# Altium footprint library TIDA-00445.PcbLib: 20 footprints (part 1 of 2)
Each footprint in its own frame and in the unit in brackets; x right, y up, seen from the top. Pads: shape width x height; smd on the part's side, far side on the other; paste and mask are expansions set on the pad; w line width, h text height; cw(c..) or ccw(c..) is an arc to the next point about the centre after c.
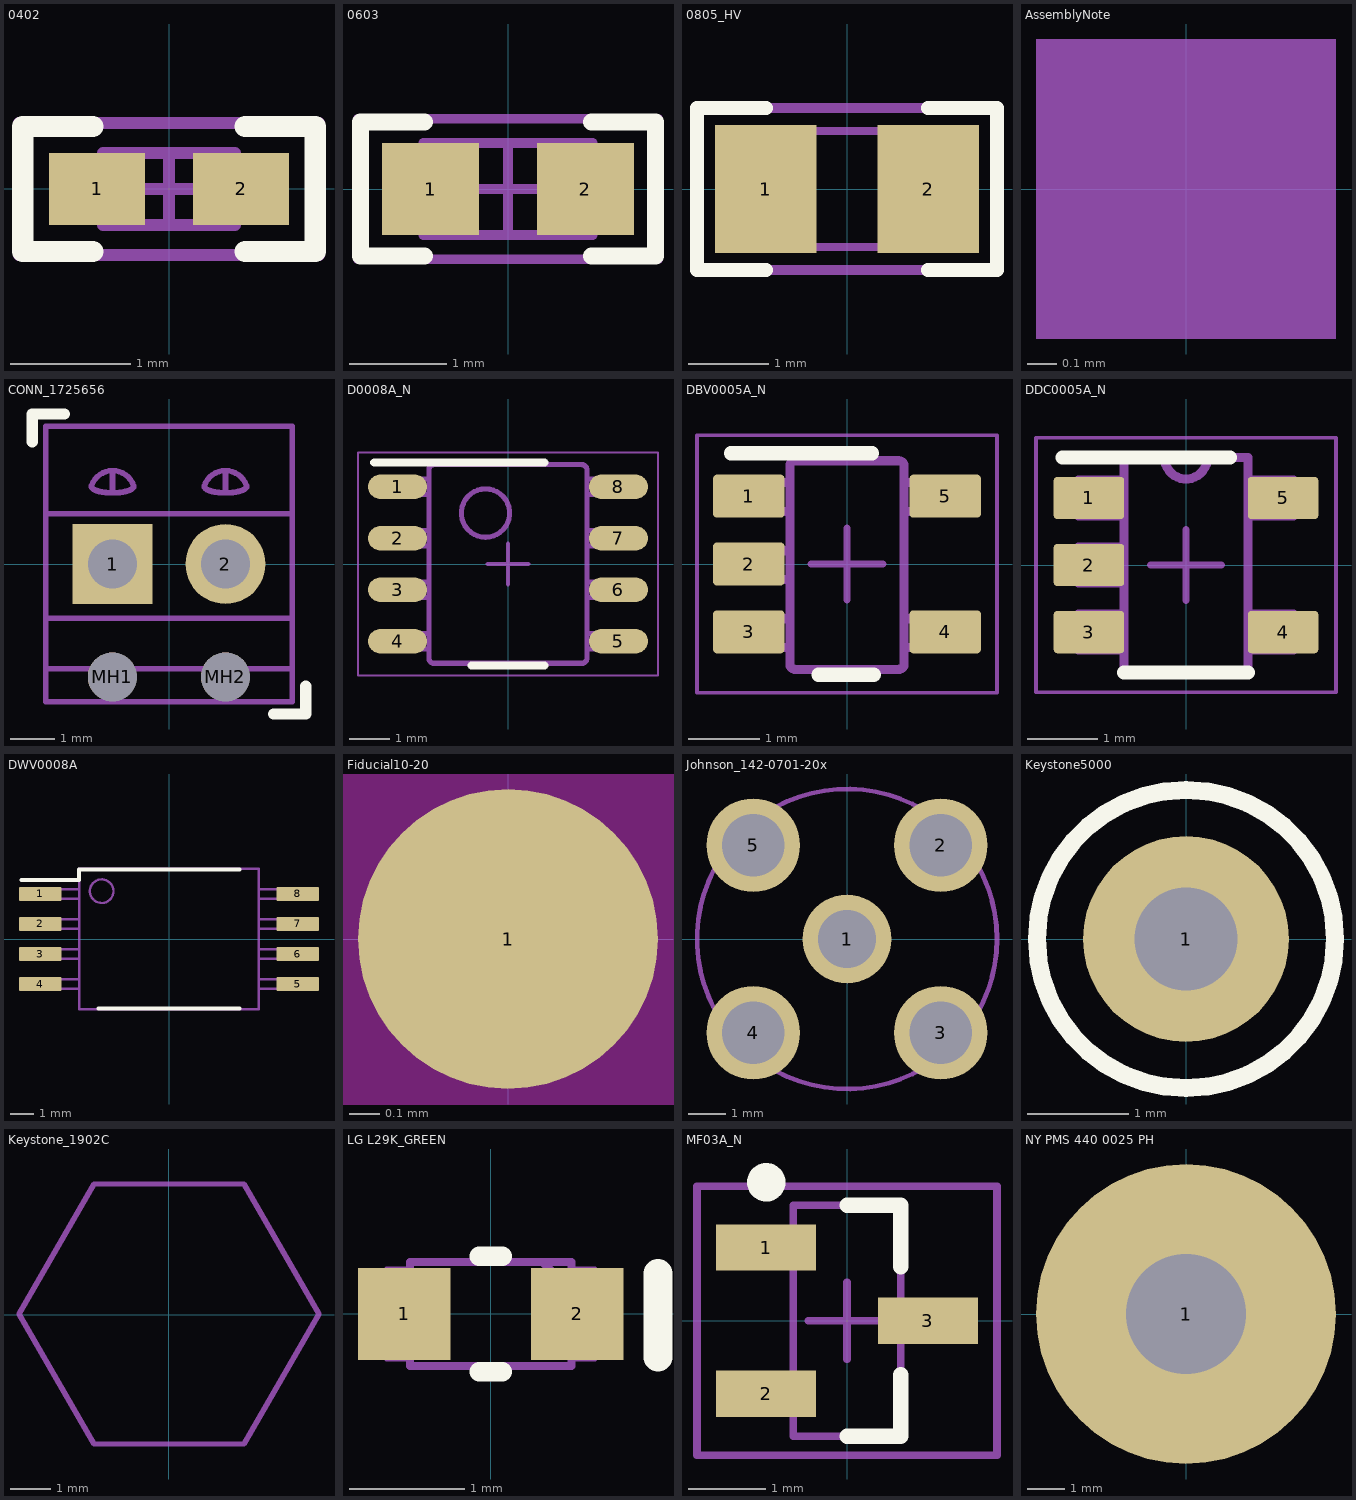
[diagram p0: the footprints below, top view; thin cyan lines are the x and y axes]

## 0402 [mm] "0402 from SM-752 data"
height 0.6
pads (2):
  rect 0.8x0.6 smd: 1(-0.6,0) 2(0.6,0)
Top Overlay:
  lines w0.178: -0.635,-0.521 -1.219,-0.521 -1.219,0.521 -0.635,0.521 ; 0.635,-0.521 1.219,-0.521 1.219,0.521 0.635,0.521
Mechanical 5:
  lines w0.1: -1.25,-0.55 -1.25,0.55 1.25,0.55 1.25,-0.55 -1.25,-0.55
  text ".Designator" at 0.483,0.432 h0.76
Mechanical 13:
  lines w0.1: -0.35,-0.3 -0.35,0.3 ; 0.35,-0.3 0.35,0.3 ; -0.55,-0.3 0.55,-0.3 0.55,0.3 -0.55,0.3 -0.55,-0.3
Mechanical 15:
  lines w0.1: -0.3,0 0.3,0 ; 0,-0.3 0,0.3 ; -1.25,-0.55 1.25,-0.55 1.25,0.55 -1.25,0.55 -1.25,-0.55
3D body: height 0.6, standoff 0, extent 0.351,-0.299 0.549,0.299
3D body: height 0.6, standoff 0, extent -0.349,-0.299 0.349,0.299
3D body: height 0.6, standoff 0, extent -0.549,-0.299 -0.351,0.299

## 0603 [mm] "0603 from SM-752 data"
height 0.85
pads (2):
  rect 1x0.95 smd: 1(-0.8,0) 2(0.8,0)
Top Overlay:
  lines w0.178: -0.864,-0.691 -1.524,-0.691 -1.524,0.693 -0.864,0.693 ; 0.864,-0.691 1.524,-0.691 1.524,0.693 0.864,0.693
Mechanical 5:
  lines w0.1: -1.55,-0.725 1.55,-0.725 1.55,0.725 -1.55,0.725 -1.55,-0.725
  text ".Designator" at -0.584,-0.356 h0.76
Mechanical 13:
  lines w0.1: -0.55,-0.475 -0.55,0.475 ; 0.55,-0.475 0.55,0.475 ; -0.875,-0.475 -0.875,0.475 0.875,0.475 0.875,-0.475 -0.875,-0.475
Mechanical 15:
  lines w0.1: -0.475,0 0.475,0 ; 0,-0.475 0,0.475 ; -1.55,-0.725 -1.55,0.725 1.55,0.725 1.55,-0.725 -1.55,-0.725
3D body: height 0.85, standoff 0, extent 0.551,-0.474 0.874,0.474
3D body: height 0.85, standoff 0, extent -0.549,-0.474 0.549,0.474
3D body: height 0.85, standoff 0, extent -0.874,-0.474 -0.551,0.474

## 0805_HV [mil] "0805 with 30mil clearance between pads"
height 57.09
pads (2):
  rect 50x63 smd: 1(-40,0) 2(40,0)
Top Overlay:
  lines w7: -40,-40 -74,-40 -74,0 -74,40 -40,40 ; 40,-40 74,-40 74,0 74,40 40,40
Mechanical 5:
  lines w5: -74,-40 -74,40 74,40 74,-40 -74,-40
  text ".Designator" at 24,17 h30
Mechanical 13:
  lines w3.94: -25.59,-28.54 -25.59,28.54 ; 25.59,-28.54 25.59,28.54 ; -43.31,-28.54 -43.31,28.54 43.31,28.54 43.31,-28.54 -43.31,-28.54
3D body: height 57.09, standoff 0, extent 25.61,-28.52 43.29,28.52
3D body: height 57.09, standoff 0, extent -25.57,-28.52 25.57,28.52
3D body: height 57.09, standoff 0, extent -43.29,-28.52 -25.61,28.52

## AssemblyNote [mm] "Assembly Note"
Mechanical 5:
  rectangle: -0.508,-0.508 0.508,0.508
  text ".Designator" at -4.191,-0.508 h0.76
  text ".Comment" at 1.143,-0.508 h0.76

## CONN_1725656 [mm] "Phoenix Contact"
height 8.5
pads (4):
  rect 1.8x1.8 hole 1.1: 1(-1.27,0)
  round 1.8 hole 1.1: 2(1.27,0)
  round 1.1 hole 1.1 unplated mask+0.254: MH1(-1.275,-2.54) MH2(1.27,-2.54)
Top Overlay:
  lines w0.254: -3.075,2.75 -3.075,3.375 -2.35,3.375 ; 2.35,-3.375 3.075,-3.375 3.075,-2.75
Mechanical 5:
  drawing of 157 lines, arcs and shapes, not listed
  text ".Designator" at 0.711,0.279 h0.76
3D body: height 8.52, standoff -3.48, extent -2.77,-3.1 2.77,3.1

## D0008A_N [mm] "SOIC, 8-Leads, Body 4.9x3.9mm, Pitch 1.27mm, IPC Medium Density"
height 1.75
pads (8):
  oval 1.45x0.6 smd: 1(-2.725,1.905) 2(-2.725,0.635) 3(-2.725,-0.635) 4(-2.725,-1.905) 5(2.725,-1.905) 6(2.725,-0.635) 7(2.725,0.635) 8(2.725,1.905)
Top Overlay:
  lines w0.2: -3.3,2.5 0.9,2.5 ; -0.9,-2.5 0.9,-2.5
Mechanical 5:
  lines w0.127: -2.375,-2.095 -1.995,-2.095 -1.952,-2.095 -1.952,-1.715 -1.995,-1.715 -2.375,-1.715 ; -2.375,-2.095 -2.589,-2.095 -3.002,-2.095 -3.002,-1.715 -2.589,-1.715 -2.375,-1.715 ; -2.375,-2.095 -2.375,-1.715 ; -2.375,-0.825 -1.995,-0.825 -1.952,-0.825 -1.952,-0.445 -1.995,-0.445 -2.375,-0.445 ; -2.375,-0.825 -2.589,-0.825 -3.002,-0.825 -3.002,-0.445 -2.589,-0.445 -2.375,-0.445 ; -2.375,-0.825 -2.375,-0.445 ; -2.375,0.445 -1.995,0.445 -1.952,0.445 -1.952,0.825 -1.995,0.825 -2.375,0.825 ; -2.375,0.445 -2.589,0.445 -3.002,0.445 -3.002,0.825 -2.589,0.825 -2.375,0.825 ; -2.375,0.445 -2.375,0.825 ; -2.375,1.715 -1.995,1.715 -1.952,1.715 -1.952,2.095 -1.995,2.095 -2.375,2.095 ; -2.375,1.715 -2.589,1.715 -3.002,1.715 -3.002,2.095 -2.589,2.095 -2.375,2.095 ; -2.375,1.715 -2.375,2.095 ; -0.332,-2.45 -1.825,-2.45 -1.826,-2.45 cw(c-1.825,-2.323) -1.952,-2.324 -1.952,-2.323 -1.952,2.323 -1.952,2.324 cw(c-1.825,2.323) -1.826,2.45 -1.825,2.45 -0.332,2.45 ; -0.332,-2.45 -0.182,-2.45 ; -0.332,-2.45 -0.182,-2.45 ; -0.332,2.45 -0.182,2.45 ; -0.332,2.45 -0.182,2.45 ; -0.182,-2.45 0.178,-2.45 ; -0.182,2.45 0.178,2.45 ; 0.178,-2.45 0.328,-2.45 ; 0.178,-2.45 0.328,-2.45 ; 0.178,2.45 0.328,2.45 ; 0.178,2.45 0.328,2.45 ; 0.328,-2.45 1.821,-2.45 1.822,-2.45 ccw(c1.821,-2.323) 1.948,-2.324 1.948,-2.323 1.948,2.323 1.948,2.324 ccw(c1.821,2.323) 1.822,2.45 1.821,2.45 0.328,2.45 ; 2.371,-2.095 2.585,-2.095 2.998,-2.095 2.998,-1.715 2.585,-1.715 2.371,-1.715 ; 2.371,-2.095 1.991,-2.095 1.948,-2.095 1.948,-1.715 1.991,-1.715 2.371,-1.715 ; 2.371,-2.095 2.371,-1.715 ; 2.371,-0.825 2.585,-0.825 2.998,-0.825 2.998,-0.445 2.585,-0.445 2.371,-0.445 ; 2.371,-0.825 1.991,-0.825 1.948,-0.825 1.948,-0.445 1.991,-0.445 2.371,-0.445 ; 2.371,-0.825 2.371,-0.445 ; 2.371,0.445 2.585,0.445 2.998,0.445 2.998,0.825 2.585,0.825 2.371,0.825 ; 2.371,0.445 1.991,0.445 1.948,0.445 1.948,0.825 1.991,0.825 2.371,0.825 ; 2.371,0.445 2.371,0.825 ; 2.371,1.715 2.585,1.715 2.998,1.715 2.998,2.095 2.585,2.095 2.371,2.095 ; 2.371,1.715 1.991,1.715 1.948,1.715 1.948,2.095 1.991,2.095 2.371,2.095 ; 2.371,1.715 2.371,2.095 ; -0.555,0.659 cw(c-0.555,1.256) -0.555,1.853 cw(c-0.555,1.256) -0.555,0.659
  text ".Designator" at -1.625,-0.625 h0.89
Mechanical 15:
  lines w0.05: -3.7,-2.75 3.7,-2.75 3.7,2.75 -3.7,2.75 -3.7,-2.75
  lines w0.1: -0.5,0 0.5,0 ; 0,-0.5 0,0.5
3D body: height 1.63, standoff 0, extent -3,-2.45 3,2.45

## DBV0005A_N [mm] "SOT23, 5-Leads, Body 2.9x1.6mm, Pitch 0.95mm, Lead Span 2.8mm, IPC Medium Density"
height 1.45
pads (5):
  rrect17% 1x0.6 smd: 1(-1.375,0.95) 2(-1.375,0) 3(-1.375,-0.95) 4(1.375,-0.95) 5(1.375,0.95)
Top Overlay:
  lines w0.2: -1.625,1.55 0.35,1.55 ; -0.4,-1.55 0.375,-1.55
Mechanical 5:
  lines w0.127: -0.801,1.371 cw(c-0.725,1.37) -0.725,1.446 ; -0.801,1.37 -0.801,1.371 ; -0.801,1.37 -0.801,-1.399 -0.801,-1.4 ccw(c-0.725,-1.399) -0.725,-1.475 ; -0.725,-1.475 0.723,-1.475 0.724,-1.475 ccw(c0.723,-1.399) 0.799,-1.4 0.799,-1.399 0.799,1.37 ; -0.725,-1.475 -0.725,-1.475 ; -0.725,1.446 -0.725,1.446 ; -0.725,1.446 0.723,1.446 0.724,1.446 cw(c0.723,1.37) 0.799,1.371 ; 0.799,1.37 0.799,1.371 ; -1.423,-1.167 -1.423,-0.767 -1.199,-0.767 -1.105,-0.767 -1.088,-0.767 -0.835,-0.767 -0.801,-0.767 -0.801,-1.167 -0.835,-1.167 -1.088,-1.167 -1.105,-1.167 -1.199,-1.167 -1.423,-1.167 ; -1.423,-0.215 -1.423,0.186 -1.199,0.186 -1.105,0.186 -1.088,0.186 -0.835,0.186 -0.801,0.186 -0.801,-0.215 -0.835,-0.215 -1.088,-0.215 -1.105,-0.215 -1.199,-0.215 -1.423,-0.215 ; -1.423,0.738 -1.423,1.138 -1.199,1.138 -1.105,1.138 -1.088,1.138 -0.835,1.138 -0.801,1.138 -0.801,0.738 -0.835,0.738 -1.088,0.738 -1.105,0.738 -1.199,0.738 -1.423,0.738 ; 0.799,-1.167 0.834,-1.167 1.087,-1.167 1.103,-1.167 1.198,-1.167 1.422,-1.167 1.422,-0.767 1.198,-0.767 1.103,-0.767 1.087,-0.767 0.834,-0.767 0.799,-0.767 0.799,-1.167 ; 0.799,0.738 0.834,0.738 1.087,0.738 1.103,0.738 1.198,0.738 1.422,0.738 1.422,1.138 1.198,1.138 1.103,1.138 1.087,1.138 0.834,1.138 0.799,1.138 0.799,0.738
  text ".Designator" at 0.305,-0.533 h0.76
Mechanical 15:
  lines w0.05: -2.1,-1.8 -2.1,1.8 2.1,1.8 2.1,-1.8 -2.1,-1.8
  lines w0.1: -0.5,0 0.5,0 ; 0,-0.5 0,0.5
3D body: height 1.09, standoff 0, extent -1.422,-1.46 1.422,1.461

## DDC0005A_N [mm]
height 1.1
pads (5):
  rrect17% 1x0.6 smd: 1(-1.375,0.95) 2(-1.375,0) 3(-1.375,-0.95) 4(1.375,-0.95) 5(1.375,0.95)
Top Overlay:
  lines w0.2: -1.75,1.525 0.625,1.525 ; -0.876,-1.524 0.876,-1.524
Mechanical 5:
  lines w0.127: -0.305,1.524 ccw(c0,1.524) 0.305,1.524 ; -1.524,-1.204 -1.524,-0.696 -0.876,-0.696 -0.876,-1.204 -1.524,-1.204 ; -1.524,-0.254 -1.524,0.254 -0.876,0.254 -0.876,-0.254 -1.524,-0.254 ; -1.524,0.696 -1.524,1.204 -0.876,1.204 -0.876,0.696 -1.524,0.696 ; -0.876,-1.524 0.876,-1.524 0.876,1.524 -0.876,1.524 -0.876,-1.524 ; 0.876,-1.204 0.876,-0.696 1.524,-0.696 1.524,-1.204 0.876,-1.204 ; 0.876,0.696 0.876,1.204 1.524,1.204 1.524,0.696 0.876,0.696
  text ".Designator" at -0.356,0.635 h0.76
Mechanical 15:
  lines w0.05: -2.125,-1.8 2.125,-1.8 2.125,1.8 -2.125,1.8 -2.125,-1.8
  lines w0.1: -0.5,0 0.5,0 ; 0,-0.5 0,0.5
3D body: height 1.1, standoff 0, extent -1.405,-1.45 1.406,1.45

## DWV0008A [mm] "SOIC, 8-Leads, Body 5.95x7.6mm (max), Pitch 1.27mm"
height 2.8
pads (8):
  rrect17% 1.8x0.6 smd: 1(-5.45,1.905) 2(-5.45,0.635) 3(-5.45,-0.635) 4(-5.45,-1.905) 5(5.45,-1.905) 6(5.45,-0.635) 7(5.45,0.635) 8(5.45,1.905)
Top Overlay:
  lines w0.17: -6.25,2.5 -3.8,2.5 -3.8,2.95 2.975,2.95 ; -2.975,-2.95 2.975,-2.95
Mechanical 5:
  circle w0.1: c-2.85,2.025 r0.5
  lines w0.1: -3.805,-2.105 -5.8,-2.105 -5.8,-1.705 -3.805,-1.705 ; -3.805,-0.835 -5.8,-0.835 -5.8,-0.435 -3.805,-0.435 ; -3.805,0.435 -5.8,0.435 -5.8,0.835 -3.805,0.835 ; -3.805,1.705 -5.8,1.705 -5.8,2.105 -3.805,2.105 ; 3.805,-2.105 5.8,-2.105 5.8,-1.705 3.805,-1.705 ; 3.805,-0.835 5.8,-0.835 5.8,-0.435 3.805,-0.435 ; 3.805,0.435 5.8,0.435 5.8,0.835 3.805,0.835 ; 3.805,1.705 5.8,1.705 5.8,2.105 3.805,2.105 ; -3.8,-2.975 -3.8,2.975 3.8,2.975 3.8,-2.975 -3.8,-2.975
  text ".Designator" at -2.8,-0.8 h0.76
3D body: height 2.67, standoff -0.03, extent -5.768,-2.925 5.768,2.925

## Fiducial10-20 [mm]
height 13
pads (1):
  round 1 smd mask+0.5: 1(0,0)
Top Layer keep-out:
  circle w1.178: c0,0 r0.5

## Johnson_142-0701-20x [mil] "Johnson Components recommended land pattern"
height 375
pads (5):
  round 95 hole 62: 1(0,0)
  round 100 hole 67: 2(100,100) 3(100,-100) 4(-100,-100) 5(-100,100)
Mechanical 5:
  circle w5: c0,0 r160
  text ".Designator" at -64,-25 h30
3D body: height 375, standoff -155, extent -155.99,-155.8 156.01,155.8

## Keystone5000 [mil] "For Keystone 500x miniature loop terminals"
height 181.1
pads (1):
  round 80 hole 40: 1(0,0)
Top Overlay:
  circle w7: c0,0 r58
Mechanical 5:
  circle w5: c0,0 r58.31
  text ".Designator" at -33,-15 h30
3D body: height 181.97, standoff -118.11, extent -49,-49 49.04,49.24

## Keystone_1902C [mil] "Hex Standoff, 4-40 threaded, nylon"
height 500
pads (1):
  round 1 on Mech3: 0(0,0)
Mechanical 5:
  lines w5: -145.29,0.49 -72.56,126.47 72.92,126.47 145.65,0.49 72.92,-125.49 -72.56,-125.49 -145.29,0.49
  text ".Designator" at -60,-20 h30
3D body: height 501, standoff 1, extent -144.95,-125.98 146,125.98

## LG L29K_GREEN [mm] "OSRAM"
height 0.67
pads (2):
  rect 0.8x0.8 smd paste-0.4: 1(-0.75,0) 2(0.75,0)
Top Overlay:
  lines w0.17: -0.1,-0.5 0.1,-0.5 ; -0.1,0.5 0.1,0.5
  lines w0.25: 1.45,-0.375 1.45,0.35
Top Paste:
  rectangle: -1.1,-0.35 -0.5,0.35
  rectangle: 0.5,-0.35 1.1,0.35
Mechanical 5:
  lines w0.07: 0.7,0.375 0.9,0.375 0.9,-0.375 0.7,-0.375 ; 0.7,-0.375 0.7,0.2 ; 0.7,-0.375 0.7,-0.45 -0.7,-0.45 -0.7,-0.375 -0.9,-0.375 -0.9,0.375 -0.7,0.375 -0.7,0.45 0.7,0.45 ; 0.7,0.2 0.45,0.45 0.7,0.45 ; 0.7,0.2 0.7,0.45
  text ".Designator" at 0.66,-0.737 h0.76
3D body: height 0.18, standoff 0, extent -0.899,-0.374 -0.701,0.374
3D body: height 0.18, standoff 0, extent 0.701,-0.374 0.899,0.374
3D body: height 0.18, standoff 0, extent -0.699,-0.449 0.699,0.449
3D body: height 0.67, standoff 0.18, extent -0.699,-0.449 0.699,0.449
3D body: height 0.67, standoff 0.65, extent 0.451,0.201 0.699,0.449

## MF03A_N [mm] "SOT23, 3-Leads, Body 2.9x1.3mm, Pitch 0.95mm, Lead Span 2.4mm, IPC Medium Density"
height 1.12
pads (3):
  rect 1.3x0.6 smd: 1(-1.05,0.95) 2(-1.05,-0.95) 3(1.05,0)
Top Overlay:
  circle w0.25: c-1.05,1.8 r0.125
  lines w0.2: 0,-1.5 0.7,-1.5 0.7,-0.7 ; 0,1.5 0.7,1.5 0.7,0.7
Mechanical 5:
  text ".Designator" at 0,0.381 h0.76
Mechanical 13:
  lines w0.1: -0.7,-1.5 -0.7,1.5 0.7,1.5 0.7,-1.5 -0.7,-1.5
Mechanical 15:
  lines w0.1: -0.5,0 0.5,0 ; 0,-0.5 0,0.5 ; -1.95,-1.75 -1.95,1.75 1.95,1.75 1.95,-1.75 -1.95,-1.75
3D body: height 1.12, standoff 0, extent -0.7,-1.5 0.7,1.5

## NY PMS 440 0025 PH [mm] "4-40 nylon screw and mounting hole"
height 1.905
pads (1):
  round 8 hole 3.2 unplated: 1(0,0)
Mechanical 5:
  circle w0.127: c0,0 r3.789
  text ".Designator" at -0.686,-0.508 h0.76
3D body: height 2.69, standoff -8.74, extent -3.302,-3.3 3.296,3.3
